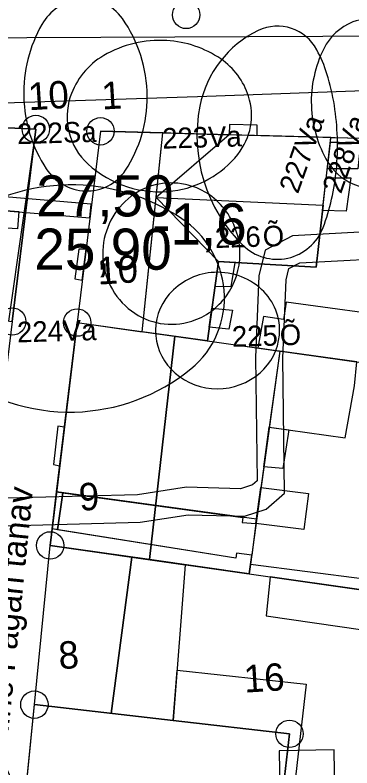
# Model space of a CAD drawing. Extents: x 738423 to 738903, y 6589762 to 6590172.
# Drawn here: x 738636.7 to 738661.3, y 6589894.3 to 6589949.3 of the extents above; entities that cross this region are included whole.
import ezdxf

# ---------------------------------------------------------------- set-up
doc = ezdxf.new("R2010")
doc.units = 0
for name, color, linetype in [('_1927_hoonestus', 7, 'Continuous'), ('_1927_katuse_kalded', 7, 'Continuous'), ('_1927_koordin_punktid_nr', 7, 'Continuous'), ('_1927_krundi_piir', 7, 'Continuous'), ('_a_ajalooline_maapind', 7, 'Continuous'), ('_a_olol_maapind', 7, 'Continuous'), ('_ajalooline_liivavall_linnamuur', 7, 'Continuous'), ('_arheol_Rüütli8_tranžee', 7, 'Continuous'), ('a_dendro_II_Vkl_puu', 7, 'Continuous'), ('a_dendro_III_vk_puu', 7, 'Continuous'), ('a_dendro_IV_vk_puu', 7, 'Continuous'), ('a_dendro_puu_nr', 7, 'Continuous'), ('Default', 7, 'Continuous'), ('plan_ala', 7, 'Continuous'), ('v_olol_kitsendus_tehnov', 7, 'Continuous'), ('v_vormistus_tekst', 7, 'Continuous')]:
    doc.layers.add(name, color=color, linetype=linetype)

# ---------------------------------------------------------------- blocks, each defined once
blk = doc.blocks.new('_U638')
at = {"layer": 'Default'}
for centre, radius, start, end in [((0.0017785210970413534, -0.00597414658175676), 0.01618526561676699, 99.23130900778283, 132.97828324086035), ((0.0017967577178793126, -0.006086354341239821), 0.016298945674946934, 62.43823725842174, 99.23130900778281), ((0.002383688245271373, -0.0049618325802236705), 0.015030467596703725, 24.06586474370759, 62.43823725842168), ((0.0009222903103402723, -0.005055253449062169), 0.014929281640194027, 132.97828324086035, 168.16056229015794), ((0.0028454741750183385, -0.004755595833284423), 0.014524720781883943, 325.34619089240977, 24.065864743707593), ((0.00048369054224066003, -0.004963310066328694), 0.0144811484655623, 168.16056229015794, 220.24997545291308), ((0.0015713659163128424, -0.003874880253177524), 0.016073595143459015, 269.78694623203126, 325.3461908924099), ((0.0015707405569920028, -0.004043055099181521), 0.01590541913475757, 220.24997545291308, 269.78694623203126)]:
    blk.add_arc(centre, radius, start, end, dxfattribs=at)
blk = doc.blocks.new('_U669')
at = {"layer": 'Default'}
for centre, radius, start, end in [((0.0013687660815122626, -0.012033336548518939), 0.02014369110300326, 95.80235597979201, 127.52069204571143), ((0.00138672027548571, -0.012210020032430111), 0.02032128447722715, 64.69041171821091, 95.80235597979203), ((0.006946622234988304, -0.0004530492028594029), 0.0073159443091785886, 11.59312788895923, 64.69041171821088), ((-0.0065460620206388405, -0.0017262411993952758), 0.007148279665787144, 127.52069204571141, 182.13236722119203), ((0.007548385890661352, -0.0003296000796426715), 0.006701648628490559, 309.4656160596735, 11.593127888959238), ((-0.006991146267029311, -0.001742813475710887), 0.006702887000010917, 182.132367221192, 241.07678504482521), ((-0.0008433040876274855, 0.00986278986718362), 0.019904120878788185, 274.6216381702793, 309.46561605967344), ((-0.0008094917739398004, 0.00944451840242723), 0.019484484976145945, 241.0767850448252, 274.6216381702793)]:
    blk.add_arc(centre, radius, start, end, dxfattribs=at)
blk = doc.blocks.new('_U675')
at = {"layer": 'Default'}
for centre, radius, start, end in [((-0.004010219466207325, -0.005289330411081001), 0.022430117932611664, 83.17249233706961, 139.71987345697), ((-0.003192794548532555, 0.0015379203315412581), 0.015554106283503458, 29.991203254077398, 83.1724923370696), ((-0.01565643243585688, 0.004580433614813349), 0.00716425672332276, 139.71987345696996, 253.60922779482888), ((0.004642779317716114, 0.006060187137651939), 0.0065071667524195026, 302.4080543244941, 29.99120325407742), ((-0.0029151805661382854, 0.0179659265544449), 0.02060927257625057, 291.7625453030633, 302.4080543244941), ((-0.007015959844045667, 0.028238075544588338), 0.03166971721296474, 283.17919195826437, 291.76254530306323), ((-0.008592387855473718, 0.028596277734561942), 0.03219746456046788, 253.6092277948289, 269.0233524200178), ((-0.008491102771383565, 0.034537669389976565), 0.038139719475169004, 269.0233524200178, 283.17919195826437)]:
    blk.add_arc(centre, radius, start, end, dxfattribs=at)
blk = doc.blocks.new('_U676')
at = {"layer": 'Default'}
for centre, radius, start, end in [((0.0013323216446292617, -0.011065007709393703), 0.01717769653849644, 96.18195829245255, 125.09681027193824), ((0.0013531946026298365, -0.011257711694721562), 0.017371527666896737, 67.84269756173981, 96.18195829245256), ((0.00487309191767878, -0.0026140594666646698), 0.008038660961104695, 25.660167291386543, 67.84269756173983), ((-0.004077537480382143, -0.003366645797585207), 0.007768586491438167, 125.09681027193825, 168.68173119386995), ((0.0066277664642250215, -0.00177109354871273), 0.0060920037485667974, 315.85637789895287, 25.66016729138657), ((-0.005765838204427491, -0.0030287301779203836), 0.006046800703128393, 168.68173119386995, 234.48463763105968), ((-0.0003586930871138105, 0.005009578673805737), 0.015827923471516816, 274.27278411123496, 315.85637789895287), ((-0.00032744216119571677, 0.004591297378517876), 0.015408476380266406, 234.48463763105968, 274.27278411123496)]:
    blk.add_arc(centre, radius, start, end, dxfattribs=at)
blk = doc.blocks.new('_U672')
at = {"layer": 'Default'}
for centre, radius, start, end in [((-0.002101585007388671, 0.008719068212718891), 0.013254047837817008, 88.3470711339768, 146.6623908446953), ((-0.0021311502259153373, 0.007694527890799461), 0.014279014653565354, 39.22630250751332, 88.34707113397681), ((-0.01341153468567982, -0.0015141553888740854), 0.028840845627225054, 5.215032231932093, 39.22630250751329), ((0.010393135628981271, 0.000499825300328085), 0.02820978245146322, 146.6623908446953, 185.68101847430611), ((-0.013432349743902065, -0.0015160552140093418), 0.028861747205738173, 330.3262965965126, 5.215032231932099), ((0.010167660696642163, 0.0004773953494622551), 0.027983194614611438, 185.68101847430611, 223.49376727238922), ((-0.0006298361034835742, -0.008810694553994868), 0.014126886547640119, 279.58281790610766, 330.3262965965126), ((-0.0004907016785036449, -0.009634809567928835), 0.013291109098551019, 223.49376727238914, 279.5828179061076)]:
    blk.add_arc(centre, radius, start, end, dxfattribs=at)
blk = doc.blocks.new('_U674')
at = {"layer": 'Default'}
for centre, radius, start, end in [((-4.7495149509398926e-05, 0.0015609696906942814), 0.010475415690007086, 95.04208340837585, 147.46260524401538), ((-4.7512575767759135e-05, 0.0015611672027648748), 0.010475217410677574, 44.52272473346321, 95.04208340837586), ((0.0004706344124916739, 0.0020707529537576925), 0.009748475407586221, 352.0159719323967, 44.52272473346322), ((-0.00066322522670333, 0.0019537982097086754), 0.009745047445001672, 147.4626052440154, 201.96834625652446), ((0.000283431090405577, 0.0020970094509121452), 0.009937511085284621, 312.4366755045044, 352.0159719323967), ((-0.0004735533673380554, 0.0020303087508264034), 0.009949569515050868, 201.96834625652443, 238.6134967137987), ((-0.0001526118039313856, 0.002573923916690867), 0.010583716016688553, 274.1334174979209, 312.43667550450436), ((-0.0001514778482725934, 0.0025582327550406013), 0.010567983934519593, 238.61349671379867, 274.1334174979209)]:
    blk.add_arc(centre, radius, start, end, dxfattribs=at)
blk = doc.blocks.new('_U673')
at = {"layer": 'Default'}
for centre, radius, start, end in [((0.0006931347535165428, -5.0993295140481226e-05), 0.008172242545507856, 99.58552965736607, 143.60493032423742), ((0.0006764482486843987, 4.781499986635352e-05), 0.008072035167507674, 53.05835449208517, 99.58552965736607), ((-0.00011276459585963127, -0.0010017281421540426), 0.009385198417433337, 10.084393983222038, 53.05835449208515), ((0.0017428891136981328, -0.000824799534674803), 0.00947637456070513, 143.60493032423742, 184.33770636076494), ((-0.00021638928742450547, -0.001020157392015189), 0.009490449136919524, 321.7625350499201, 10.084393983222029), ((0.0018031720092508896, -0.0008202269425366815), 0.009536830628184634, 184.3377063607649, 225.10763018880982), ((0.0008845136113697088, -0.0017423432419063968), 0.00823520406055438, 225.10763018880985, 269.13699667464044), ((0.0008823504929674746, -0.0018859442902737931), 0.008091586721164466, 269.13699667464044, 321.76253504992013)]:
    blk.add_arc(centre, radius, start, end, dxfattribs=at)
blk = doc.blocks.new('_U671')
at = {"layer": 'Default'}
for centre, radius, start, end in [((-0.003374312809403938, 0.004949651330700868), 0.009317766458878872, 75.98881495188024, 141.8130774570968), ((-0.003768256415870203, 0.003370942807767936), 0.010944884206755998, 34.56599988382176, 75.98881495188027), ((0.0014665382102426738, 0.0011420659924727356), 0.015476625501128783, 141.81307745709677, 191.684193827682), ((-0.008227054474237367, 0.0002989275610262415), 0.01635950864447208, 0.9371401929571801, 34.56599988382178), ((-0.007523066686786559, 0.00031044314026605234), 0.015655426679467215, 330.0649598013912, 0.9371401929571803), ((0.0005393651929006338, 0.0009503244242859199), 0.01452983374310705, 191.68419382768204, 235.64850716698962), ((-0.0030046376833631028, -0.0022914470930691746), 0.01044140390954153, 292.0232036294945, 330.0649598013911), ((-0.002510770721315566, -0.0035123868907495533), 0.009124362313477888, 235.6485071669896, 292.0232036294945)]:
    blk.add_arc(centre, radius, start, end, dxfattribs=at)

msp = doc.modelspace()

# ---------------------------------------------------------------- linework, layer by layer
at = {"layer": '_1927_hoonestus'}
for points in [[(738619.9942934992, 6589941.7670035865), (738619.5589872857, 6589936.166617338), (738619.5589872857, 6589936.166617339), (738619.5256598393, 6589935.304280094), (738628.31766578, 6589934.534553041), (738627.5826462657, 6589928.059372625), (738636.5091918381, 6589926.891104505), (738638.2396178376, 6589940.94571321), (738620.342268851, 6589941.795771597)], [(738642.9591139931, 6589940.778512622), (738641.2530402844, 6589926.815593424), (738650.7641007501, 6589925.480836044), (738651.5767516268, 6589931.271530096), (738658.7090916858, 6589930.863355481), (738659.7860125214, 6589940.335708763), (738654.3921120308, 6589940.477650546), (738654.4095715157, 6589941.231817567), (738652.3745456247, 6589941.285893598), (738652.3575455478, 6589940.531190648)], [(738659.747145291, 6589939.993841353), (738661.9526274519, 6589939.891692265), (738661.7639830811, 6589938.0275368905), (738659.5258756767, 6589938.047603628)], [(738659.7860125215, 6589940.3357087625), (738662.2758304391, 6589940.27018861), (738662.2654888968, 6589939.877201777), (738659.7471452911, 6589939.993841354)], [(738659.4496444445, 6589937.377090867), (738661.2373094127, 6589937.377090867), (738660.8977096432, 6589934.939317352), (738659.1784884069, 6589934.99206339)], [(738641.9074521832, 6589932.171458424), (738641.3680729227, 6589932.171458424), (738641.0916886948, 6589930.004285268), (738641.6315320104, 6589929.913261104)], [(738652.7676375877, 6589931.20337723), (738652.4874428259, 6589929.421674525), (738651.3215439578, 6589929.453000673), (738651.5767516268, 6589931.271530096)], [(738665.758297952, 6589929.692470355), (738665.459647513, 6589927.08831797), (738656.5091354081, 6589928.314041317), (738656.3355450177, 6589927.0464446), (738654.8545915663, 6589927.249253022), (738654.4566176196, 6589924.9626378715), (738669.5947892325, 6589922.838186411), (738670.0996549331, 6589929.448830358)], [(738651.0998201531, 6589927.873066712), (738652.6096472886, 6589927.722785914), (738652.3317929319, 6589926.3425596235), (738650.9045967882, 6589926.4819665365)], [(738641.2530402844, 6589926.815593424), (738650.7641007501, 6589925.480836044), (738656.0626882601, 6589924.737246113), (738654.3398328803, 6589912.460721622), (738639.7534828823, 6589914.458551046)], [(738661.5130182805, 6589922.201342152), (738661.6687240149, 6589923.9505097), (738656.0626882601, 6589924.737246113), (738655.2835310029, 6589919.185217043), (738660.8355600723, 6589918.406059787)], [(738640.3260424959, 6589919.176705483), (738639.8382200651, 6589919.245707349), (738639.5287579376, 6589916.453986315), (738639.9854894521, 6589916.370391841)], [(738656.71708736, 6589918.984035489), (738656.2843425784, 6589916.165939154), (738654.8765163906, 6589916.284959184), (738655.283531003, 6589919.185217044)], [(738662.2307096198, 6589908.078251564), (738653.9028397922, 6589909.158261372), (738653.8060863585, 6589908.479848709), (738667.6613666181, 6589906.503844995), (738668.3392788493, 6589914.563788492), (738663.0394642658, 6589915.202400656)], [(738654.6648059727, 6589914.776377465), (738658.142648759, 6589914.333045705), (738657.8073583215, 6589911.702763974), (738654.2931424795, 6589912.1507323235)], [(738640.1986815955, 6589914.3975741), (738639.8085051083, 6589911.694147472), (738639.4253832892, 6589911.754859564), (738639.7534828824, 6589914.458551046)], [(738640.1986815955, 6589914.3975741), (738653.349351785, 6589912.596383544), (738653.2991736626, 6589912.230028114), (738654.2931424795, 6589912.1507323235), (738653.999593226, 6589909.836674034), (738652.8889122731, 6589909.9950764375), (738652.8367885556, 6589909.629597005), (738639.8085051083, 6589911.694147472)], [(738639.4253832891, 6589911.754859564), (738639.2793661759, 6589910.5516114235), (738653.8060863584, 6589908.479848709), (738653.999593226, 6589909.836674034), (738652.8889122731, 6589909.9950764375), (738652.8367885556, 6589909.629597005)], [(738639.279366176, 6589910.5516114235), (738649.1529144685, 6589909.143471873), (738648.2717006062, 6589897.771571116), (738638.1290908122, 6589898.927727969)], [(738655.3410315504, 6589908.260938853), (738655.0571223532, 6589905.406639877), (738667.3213049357, 6589903.626637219), (738667.6613666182, 6589906.503844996)], [(738648.5572709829, 6589901.456803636), (738657.987576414, 6589900.425538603), (738653.971798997, 6589865.440014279), (738653.1607330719, 6589865.55689891), (738656.7595760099, 6589896.804037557), (738648.2717006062, 6589897.771571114)], [(738638.1290908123, 6589898.927727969), (738648.2717006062, 6589897.771571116), (738656.7595760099, 6589896.804037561), (738655.986351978, 6589890.090480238), (738642.4241395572, 6589891.652487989), (738641.9789662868, 6589887.787248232), (738637.0682383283, 6589888.257436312)]]:
    msp.add_lwpolyline(points, close=True, dxfattribs=at)
at = {"layer": '_1927_katuse_kalded'}
for points in [[(738633.2615524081, 6589941.182153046), (738638.2396178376, 6589940.94571321), (738636.2310283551, 6589926.927509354), (738632.0459190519, 6589927.475238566)], [(738642.9608680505, 6589940.777111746), (738641.2530402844, 6589926.815593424), (738646.0085705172, 6589926.148214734), (738647.5107530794, 6589940.658735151)], [(738652.3575455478, 6589940.531190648), (738647.0230372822, 6589935.947583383), (738647.5107530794, 6589940.6587351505)], [(738652.3575455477, 6589940.531190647), (738647.0230372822, 6589935.947583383), (738659.2237129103, 6589935.389847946), (738659.7860125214, 6589940.335708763)], [(738647.0230372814, 6589935.947583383), (738651.5767501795, 6589931.271519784), (738650.7641007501, 6589925.480836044), (738646.0085705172, 6589926.148214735)], [(738659.2237129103, 6589935.389847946), (738658.7090916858, 6589930.863355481), (738651.5767516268, 6589931.271530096), (738647.0230372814, 6589935.947583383)], [(738641.2530402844, 6589926.815593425), (738648.3863356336, 6589925.814525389), (738646.5427262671, 6589909.515730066), (738639.2793661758, 6589910.5516114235)], [(738648.3863356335, 6589925.814525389), (738656.06268826, 6589924.737246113), (738653.8060863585, 6589908.47984871), (738646.5427262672, 6589909.515730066)], [(738639.2793661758, 6589910.5516114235), (738645.2406163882, 6589909.70143356), (738643.74803539, 6589898.287224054), (738638.1290908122, 6589898.927727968)], [(738645.2406163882, 6589909.701433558), (738649.1529144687, 6589909.143471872), (738648.2717006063, 6589897.771571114), (738643.7480353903, 6589898.2872240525)]]:
    msp.add_lwpolyline(points, close=True, dxfattribs=at)
at = {"layer": '_1927_koordin_punktid_nr'}
for centre, radius in [((738649.2135835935, 6589949.273370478), 0.9999999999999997), ((738638.2396178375, 6589940.94571321), 0.9999999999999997), ((738642.9591139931, 6589940.778512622), 0.9999999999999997), ((738636.5091918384, 6589926.8911045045), 0.9999999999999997), ((738641.2530402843, 6589926.815593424), 0.9999999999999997), ((738639.279366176, 6589910.5516114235), 0.9999999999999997), ((738638.1290908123, 6589898.927727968), 0.9999999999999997), ((738656.7571685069, 6589896.800588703), 1)]:
    msp.add_circle(centre, radius, dxfattribs=at)
at = {"layer": '_1927_krundi_piir'}
for p, q in [((738638.1290908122, 6589898.927727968), (738656.7595760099, 6589896.804037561)), ((738656.7595760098, 6589896.804037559), (738653.160733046, 6589865.556898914))]:
    msp.add_line(p, q, dxfattribs=at)
for points in [[(738586.182705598, 6589872.620611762), (738590.9372064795, 6589898.13516685), (738590.975352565, 6589898.488217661), (738593.7110525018, 6589923.115674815), (738595.6482555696, 6589940.609766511), (738608.5799562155, 6589940.823351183), (738620.342268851, 6589941.795771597), (738638.2396178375, 6589940.94571321)], [(738638.2396178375, 6589940.94571321), (738636.5091918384, 6589926.8911045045), (738634.3211426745, 6589909.080822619), (738629.2817413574, 6589868.018556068)], [(738642.9591139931, 6589940.778512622), (738641.2530402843, 6589926.815593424), (738669.5947892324, 6589922.838186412)], [(738642.9591139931, 6589940.778512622), (738670.908755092, 6589940.043011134), (738703.6658553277, 6589939.175840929), (738699.2597677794, 6589917.23983417), (738689.9894215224, 6589918.406316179), (738669.274902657, 6589918.640213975), (738669.45830989, 6589921.006172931), (738669.5947892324, 6589922.838186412), (738670.908755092, 6589940.043011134)], [(738641.2530402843, 6589926.815593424), (738639.279366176, 6589910.5516114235), (738668.3328065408, 6589906.408085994), (738669.274902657, 6589918.640213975)], [(738699.2597677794, 6589917.23983417), (738686.9079452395, 6589860.693508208), (738653.160733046, 6589865.556898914), (738635.0048101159, 6589867.503013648), (738638.1290908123, 6589898.927727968), (738639.279366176, 6589910.5516114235)]]:
    msp.add_lwpolyline(points, dxfattribs=at)
at = {"layer": '_ajalooline_liivavall_linnamuur'}
msp.add_lwpolyline([(738708.289405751, 6589968.14747116), (738780.2257645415, 6589985.561122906), (738769.667506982, 6589952.525563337), (738767.8196994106, 6589945.734830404), (738713.208654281, 6589947.930212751), (738615.9368314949, 6589947.498858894), (738617.4577657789, 6589962.743100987), (738623.554579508, 6589962.319832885), (738622.8971321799, 6589952.276700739), (738711.4568073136, 6589955.13)], close=True, dxfattribs=at)
at = {"layer": '_arheol_Rüütli8_tranžee'}
for points in [[(738622.1085370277, 6589936.153210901), (738642.1870033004, 6589934.459372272), (738642.2717703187, 6589935.464185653), (738622.1933040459, 6589937.158024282)], [(738635.0359158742, 6589935.06264485), (738636.9867592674, 6589934.925584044), (738636.8972313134, 6589933.651295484), (738634.9463879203, 6589933.788356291)]]:
    msp.add_lwpolyline(points, close=True, dxfattribs=at)
at = {"layer": 'plan_ala'}
msp.add_lwpolyline([(738772.2221966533, 6589837.873120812), (738583.11, 6589865.669999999), (738583.11, 6589865.669999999), (738577.13, 6589865.85), (738565.7035831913, 6589866.139410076), (738565.4500000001, 6589885.77), (738564.4932191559, 6589941.052825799), (738581.9, 6589941.1499999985), (738615.11, 6589942.169999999), (738650.0499999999, 6589943.319999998), (738691.2690631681, 6589944.800325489), (738696.0901513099, 6589944.851371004), (738713.89, 6589945.129999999), (738703.51, 6589987.789999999), (738752.8799999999, 6590000.39), (738783.1408503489, 6590007.463828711), (738767.5688789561, 6589951.87996157)], close=True, dxfattribs=at)
at = {"layer": 'v_olol_kitsendus_tehnov'}
for points in [[(738673.980859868, 6589934.065020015), (738656.984348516, 6589933.151956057), (738654.9873087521, 6589932.112926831), (738654.5179945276, 6589930.2244957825), (738654.2737387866, 6589924.25607098), (738654.3885315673, 6589915.266655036), (738654.0546384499, 6589914.976434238), (738653.1865002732, 6589914.6847123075), (738649.2378045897, 6589914.798259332), (738645.6658428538, 6589914.234000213), (738634.174176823, 6589913.940901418)], [(738634.285823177, 6589911.94309858), (738645.8481571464, 6589912.237999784), (738649.3661954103, 6589912.793740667), (738653.4854997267, 6589912.675287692), (738655.0674801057, 6589913.206883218), (738656.4002048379, 6589914.365291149), (738656.2742612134, 6589924.227929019), (738656.5080054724, 6589929.939504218), (738656.7106912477, 6589930.755073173), (738657.5236514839, 6589931.178043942), (738674.0238867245, 6589932.064447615)], [(738586.6888850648, 6589865.143953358), (738591.9451522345, 6589864.37135473), (738592.5597488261, 6589882.810896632), (738660.2059563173, 6589884.29620018), (738660.0179515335, 6589895.618846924), (738656.018502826, 6589895.552438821), (738656.1404538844, 6589888.2078982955), (738592.1413769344, 6589886.802674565), (738592.1718913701, 6589887.668806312), (738591.66193984, 6589894.040728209), (738588.6389999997, 6589893.962)]]:
    msp.add_lwpolyline(points, dxfattribs=at)

# ---------------------------------------------------------------- block references
at = {"layer": 'a_dendro_II_Vkl_puu', "xscale": 500.0000000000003, "yscale": 500.0000000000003, "rotation": 85.69234851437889}
msp.add_blockref('_U671', (738647.7699789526, 6589943.330483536), dxfattribs=at)
at = {"layer": 'a_dendro_III_vk_puu', "xscale": 500.0000000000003, "yscale": 500.0000000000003, "rotation": 85.69234851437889}
for name, p in [('_U669', (738641.3710000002, 6589943.325999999)), ('_U675', (738658.734, 6589942.654999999)), ('_U676', (738661.374, 6589942.683000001)), ('_U672', (738640.577, 6589929.188)), ('_U638', (738626.7529999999, 6589890.438999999))]:
    msp.add_blockref(name, p, dxfattribs=at)
at = {"layer": 'a_dendro_IV_vk_puu', "xscale": 500.0000000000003, "yscale": 500.0000000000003, "rotation": 85.69234851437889}
for name, p in [('_U674', (738649.139, 6589931.821)), ('_U673', (738651.0179999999, 6589925.889000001))]:
    msp.add_blockref(name, p, dxfattribs=at)

# ---------------------------------------------------------------- texts
at = {"layer": '_1927_koordin_punktid_nr'}
for s, rotation, p in [('10', 3.560863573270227, (738637.7287446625, 6589942.309551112)), ('1', 3.560863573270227, (738643.0929457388, 6589942.361505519)), ('10', 3.560863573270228, (738642.7827350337, 6589929.5824081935)), ('9', 3.560863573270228, (738641.4417571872, 6589913.074734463)), ('8', 3.5608635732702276, (738639.9492465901, 6589901.514671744)), ('16', 3.5608635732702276, (738653.4852067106, 6589899.800418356))]:
    msp.add_text(s, height=1.9999999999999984, rotation=rotation, dxfattribs=at).set_placement(p)
at = {"layer": '_a_ajalooline_maapind'}
for s, p in [('-1,6', (738646.7270245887, 6589932.513727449)), ('25,90', (738638.1263213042, 6589930.678385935))]:
    msp.add_text(s, height=3, dxfattribs=at).set_placement(p)
at = {"layer": '_a_olol_maapind'}
msp.add_text('27,50', height=3, dxfattribs=at).set_placement((738638.2608661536, 6589934.565009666))
at = {"layer": 'a_dendro_puu_nr'}
for s, height, rotation, p in [('227Va', 1.4999999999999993, 70.36105075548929, (738657.377476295, 6589936.157954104)), ('228Va', 1.4999999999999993, 70.36105075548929, (738660.525058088, 6589936.157954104)), ('222Sa', 1.5, 1.7381147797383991, (738636.8880093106, 6589939.836170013)), ('223Va', 1.5, 1.7381147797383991, (738647.4882118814, 6589939.50781147)), ('Õ', 1.5, 1.7381147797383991, (738654.8300308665, 6589932.361999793)), ('226', 1.5, 1.7381147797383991, (738651.3353911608, 6589932.25595448)), ('224Va', 1.5, 1.7381147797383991, (738636.8874196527, 6589925.365327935)), ('Õ', 1.5, 1.7381147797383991, (738656.0737738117, 6589925.149215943)), ('225', 1.5, 1.7381147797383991, (738652.5791341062, 6589925.043170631))]:
    msp.add_text(s, height=height, rotation=rotation, dxfattribs=at).set_placement(p)
at = {"layer": 'v_vormistus_tekst'}
msp.add_text('ajalooline Pagari tänav', height=1.7999999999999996, rotation=84.19514024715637, dxfattribs=at).set_placement((738635.5819194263, 6589890.509699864))

doc.saveas('drawing.dxf')
